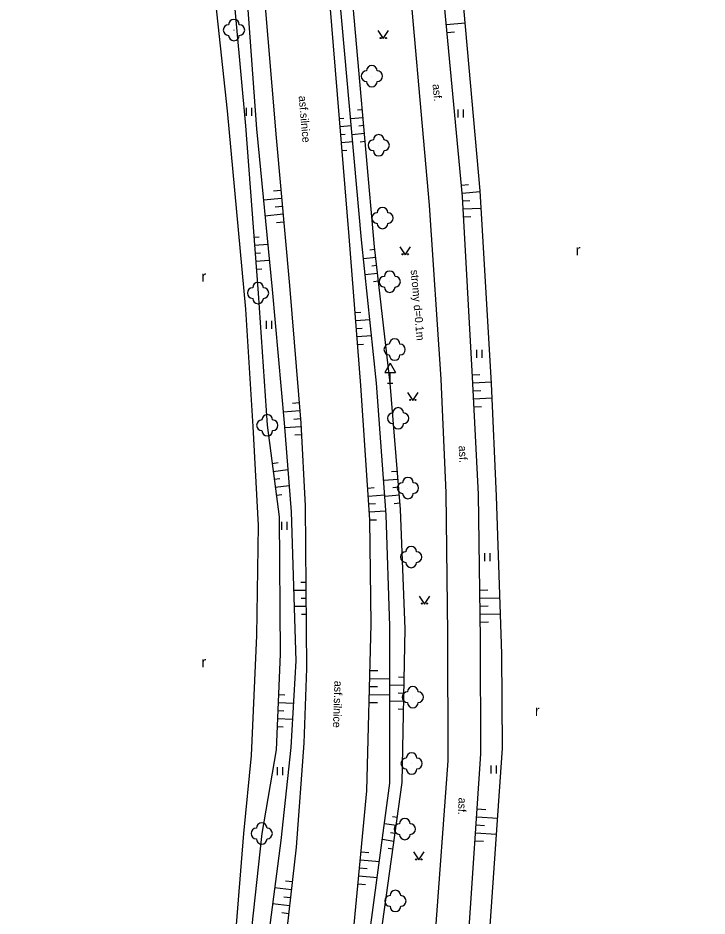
# Model space of a CAD drawing. Extents: x -545714 to -535419, y -1201788 to -1194297.
# Drawn here: x -543649.7 to -543585.1, y -1196035 to -1195950.8 of the extents above; entities that cross this region are included whole.
import ezdxf

# ---------------------------------------------------------------- set-up
doc = ezdxf.new("R2010")
doc.units = 0
for name, color, linetype in [('Vrstva 10', 7, 'Continuous'), ('Vrstva 11', 7, 'Continuous'), ('Vrstva 12', 7, 'Continuous'), ('Vrstva 13', 7, 'Continuous'), ('Vrstva 15', 7, 'Continuous'), ('Vrstva 3', 7, 'Continuous')]:
    doc.layers.add(name, color=color, linetype=linetype)

msp = doc.modelspace()

# ---------------------------------------------------------------- linework, layer by layer
at = {"layer": 'Vrstva 10'}
for p, q in [((-543614.79, -1195983.134), (-543615.29, -1195984)), ((-543614.79, -1195983.134), (-543614.29, -1195984)), ((-543615.29, -1195984), (-543614.29, -1195984)), ((-543614.79, -1195985), (-543614.79, -1195984)), ((-543615.04, -1195985), (-543614.54, -1195985))]:
    msp.add_line(p, q, dxfattribs=at)
at = {"layer": 'Vrstva 11'}
for points in [[(-543607.43, -1196037.02), (-543606.28, -1196019.77), (-543606.3, -1196009), (-543606.5, -1195995.43), (-543607.06, -1195984.44), (-543608.01, -1195967.52), (-543610.49, -1195940.94), (-543612.66, -1195916.66), (-543613.72, -1195904.08), (-543614, -1195894.09), (-543612.96, -1195887.23), (-543612.45, -1195879.29), (-543612.44, -1195876.36), (-543611.47, -1195876.49), (-543610.1, -1195878.26), (-543608.46, -1195876.99), (-543612.9, -1195869.72), (-543613.03, -1195867.25)], [(-543632.41, -1196211.07), (-543630.37, -1196193.32), (-543624.96, -1196151.17), (-543622.81, -1196132.43), (-543618.85, -1196100.43), (-543615.34, -1196072.49), (-543612.05, -1196046.99), (-543610.57, -1196036.97), (-543609.35, -1196020.42), (-543609.38, -1196008.52), (-543609.53, -1195995.3), (-543610, -1195984.65), (-543611.08, -1195968.31), (-543613.38, -1195942.54), (-543615.71, -1195916.87), (-543616.79, -1195903.73), (-543617.14, -1195895.44), (-543615.68, -1195885.08), (-543615.46, -1195880.81), (-543615.86, -1195867.87)], [(-543639.09, -1196203.64), (-543635.02, -1196171.2), (-543630.55, -1196134.22), (-543626.42, -1196101.45), (-543622.95, -1196075.4), (-543619.74, -1196048.22), (-543618.21, -1196036.42), (-543616.96, -1196023.24), (-543616.56, -1196007.59), (-543616.68, -1195997.82), (-543617.53, -1195985.22), (-543618.61, -1195971.27), (-543620.62, -1195946.9), (-543623.05, -1195920.62), (-543624.43, -1195906.58), (-543625.23, -1195895.93), (-543626.15, -1195884.51)], [(-543632.01, -1195889.02), (-543630.66, -1195904.04), (-543629.59, -1195915.71), (-543627.44, -1195938.51), (-543625.46, -1195962.01), (-543624.21, -1195975.84), (-543623.14, -1195988.77), (-543622.74, -1195996.52), (-543622.61, -1196011.77), (-543622.88, -1196018.77), (-543623.58, -1196028.52), (-543624.79, -1196039.27), (-543627.41, -1196061.04), (-543629.27, -1196076.23), (-543632.15, -1196098.41), (-543634.76, -1196118.38), (-543637.1, -1196136.86), (-543638.96, -1196152.81), (-543641.47, -1196173.25), (-543643.67, -1196191.48), (-543644.99, -1196202.76)]]:
    msp.add_lwpolyline(points, dxfattribs=at)
at = {"layer": 'Vrstva 12'}
for points in [[(-543637.35, -1195889.08), (-543636.25, -1195900.75), (-543634.27, -1195918.95), (-543632.55, -1195936.22), (-543630.06, -1195959.48), (-543628.32, -1195978.08), (-543627.64, -1195989.06), (-543627.13, -1195998.35), (-543627.3, -1196008.65), (-543627.81, -1196019.91), (-543628.52, -1196027.23), (-543629.59, -1196040.43), (-543631.56, -1196057.77), (-543633.61, -1196077.67), (-543635.95, -1196095.36), (-543638.88, -1196118.45), (-543640.59, -1196133.76), (-543643.14, -1196154.34), (-543645.07, -1196170.53), (-543648, -1196190.91), (-543649.65, -1196200.28)], [(-543620.94, -1196214.98), (-543624.31, -1196211.9), (-543626.03, -1196206.25), (-543625.47, -1196195.96), (-543620.17, -1196152.27), (-543617.52, -1196130.8), (-543613.54, -1196101.25), (-543610.23, -1196073.03), (-543606.7, -1196046.58), (-543605.55, -1196038.14), (-543604.25, -1196019.22), (-543604.31, -1196010.39), (-543604.8, -1195995.59), (-543605.27, -1195985.05), (-543606.35, -1195966.98), (-543608.76, -1195939.98), (-543609.96, -1195918.4), (-543608.87, -1195913.01), (-543606.32, -1195907.39), (-543600.46, -1195896.38), (-543598.68, -1195894.64), (-543593.62, -1195901.24), (-543585.09, -1195909.68)]]:
    msp.add_lwpolyline(points, dxfattribs=at)
for centre in [(-543629.41, -1195951.91), (-543616.49, -1195956.23), (-543615.85, -1195962.71), (-543615.5, -1195969.53), (-543614.82, -1195975.5), (-543627.16, -1195976.56), (-543614.36, -1195981.86), (-543614.03, -1195988.3), (-543626.29, -1195988.96), (-543613.11, -1195994.84), (-543612.81, -1196001.31), (-543612.65, -1196014.44), (-543612.77, -1196020.66), (-543626.81, -1196027.23), (-543613.4, -1196026.81), (-543614.29, -1196033.55)]:
    msp.add_circle(centre, 0.0005, dxfattribs=at)
for centre, start, end in [((-543629.91, -1195951.91), 89.99999, 269.99999), ((-543629.41, -1195951.41), 0, 179.99999), ((-543628.91, -1195951.91), 270, 89.99999), ((-543629.41, -1195952.41), 179.99999, 359.99999), ((-543616.99, -1195956.23), 89.99999, 269.99999), ((-543616.49, -1195955.73), 0, 179.99999), ((-543615.99, -1195956.23), 270, 89.99999), ((-543616.49, -1195956.73), 179.99999, 359.99999), ((-543616.35, -1195962.71), 89.99999, 269.99999), ((-543615.85, -1195962.21), 0, 179.99999), ((-543615.35, -1195962.71), 270, 89.99999), ((-543615.85, -1195963.21), 179.99999, 359.99999), ((-543616, -1195969.53), 89.99999, 269.99999), ((-543615.5, -1195969.03), 0, 179.99999), ((-543615, -1195969.53), 270, 89.99999), ((-543615.5, -1195970.03), 179.99999, 359.99999), ((-543615.32, -1195975.5), 89.99999, 269.99999), ((-543614.82, -1195975), 0, 179.99999), ((-543614.32, -1195975.5), 270, 89.99999), ((-543627.16, -1195976.06), 0, 179.99999), ((-543627.66, -1195976.56), 89.99999, 269.99999), ((-543626.66, -1195976.56), 270, 89.99999), ((-543614.82, -1195976), 179.99999, 359.99999), ((-543627.16, -1195977.06), 179.99999, 359.99999), ((-543614.36, -1195981.36), 0, 179.99999), ((-543614.86, -1195981.86), 89.99999, 269.99999), ((-543613.86, -1195981.86), 270, 89.99999), ((-543614.36, -1195982.36), 179.99999, 359.99999), ((-543614.03, -1195987.8), 0, 179.99999), ((-543626.79, -1195988.96), 89.99999, 269.99999), ((-543626.29, -1195988.46), 0, 179.99999), ((-543625.79, -1195988.96), 270, 89.99999), ((-543614.53, -1195988.3), 89.99999, 269.99999), ((-543613.53, -1195988.3), 270, 89.99999), ((-543614.03, -1195988.8), 179.99999, 359.99999), ((-543626.29, -1195989.46), 179.99999, 359.99999), ((-543613.61, -1195994.84), 89.99999, 269.99999), ((-543613.11, -1195994.34), 0, 179.99999), ((-543612.61, -1195994.84), 270, 89.99999), ((-543613.11, -1195995.34), 179.99999, 359.99999), ((-543612.81, -1196000.81), 0, 179.99999), ((-543613.31, -1196001.31), 89.99999, 269.99999), ((-543612.31, -1196001.31), 270, 89.99999), ((-543612.81, -1196001.81), 179.99999, 359.99999), ((-543612.65, -1196013.94), 0, 179.99999), ((-543613.15, -1196014.44), 89.99999, 269.99999), ((-543612.15, -1196014.44), 270, 89.99999), ((-543612.65, -1196014.94), 179.99999, 359.99999), ((-543612.77, -1196020.16), 0, 179.99999), ((-543613.27, -1196020.66), 89.99999, 269.99999), ((-543612.27, -1196020.66), 270, 89.99999), ((-543612.77, -1196021.16), 179.99999, 359.99999), ((-543626.81, -1196026.73), 0, 179.99999), ((-543613.9, -1196026.81), 89.99999, 269.99999), ((-543613.4, -1196026.31), 0, 179.99999), ((-543612.9, -1196026.81), 270, 89.99999), ((-543627.31, -1196027.23), 89.99999, 269.99999), ((-543626.31, -1196027.23), 270, 89.99999), ((-543613.4, -1196027.31), 179.99999, 359.99999), ((-543626.81, -1196027.73), 179.99999, 359.99999), ((-543614.79, -1196033.55), 89.99999, 269.99999), ((-543614.29, -1196033.05), 0, 179.99999), ((-543613.79, -1196033.55), 270, 89.99999), ((-543614.29, -1196034.05), 179.99999, 359.99999)]:
    msp.add_arc(centre, 0.5, start, end, dxfattribs=at)
at = {"layer": 'Vrstva 13'}
for points in [[(-543637.68, -1196204.91), (-543633.55, -1196170.77), (-543629.08, -1196133.41), (-543625.09, -1196102.26), (-543621.67, -1196075.01), (-543618.41, -1196048.88), (-543616.7, -1196036.73), (-543614.81, -1196022.52), (-543614.82, -1196007.8), (-543615.15, -1195997.35), (-543616.06, -1195985.01), (-543617.47, -1195971.56), (-543619.73, -1195946.13), (-543622.24, -1195919.83), (-543623.14, -1195907.11), (-543624.18, -1195895.5), (-543625.27, -1195884.41)], [(-543637.05, -1196204.96), (-543632.44, -1196170.19), (-543627.94, -1196133.03), (-543624.22, -1196102.84), (-543620.55, -1196074.64), (-543617.37, -1196049.43), (-543615.66, -1196036.82), (-543613.64, -1196022.43), (-543613.38, -1196008.04), (-543613.8, -1195996.84), (-543614.79, -1195985), (-543616.24, -1195972.22), (-543618.58, -1195945.75), (-543620.93, -1195921.24), (-543621.68, -1195907.9), (-543622.76, -1195895.51), (-543623.49, -1195886.82)], [(-543634.72, -1195888.98), (-543633.71, -1195902.59), (-543632.22, -1195917.58), (-543630.51, -1195936.95), (-543628.32, -1195960.9), (-543627.16, -1195976.56), (-543626.29, -1195988.96), (-543625.18, -1195997.54), (-543625.08, -1196010.41), (-543625.45, -1196019.37), (-543626.81, -1196027.23), (-543628.09, -1196039), (-543629.96, -1196058.78), (-543632.18, -1196076.05), (-543634.6, -1196096.72), (-543637.55, -1196118.36), (-543639.29, -1196135.15), (-543642.06, -1196154.03), (-543643.93, -1196171.42), (-543646.59, -1196191.4), (-543647.93, -1196200.94)], [(-543633.26, -1195889.08), (-543632.32, -1195903.25), (-543630.88, -1195916.7), (-543629.01, -1195937.51), (-543627.31, -1195961.18), (-543625.83, -1195976.22), (-543624.72, -1195988.72), (-543624.05, -1195997.08), (-543623.61, -1196011.03), (-543624.09, -1196019.16), (-543625.02, -1196027.87), (-543626.53, -1196039.42), (-543628.92, -1196059.75), (-543630.9, -1196076.27), (-543633.64, -1196097.53), (-543636.3, -1196118.46), (-543638.55, -1196135.87), (-543640.73, -1196153.47), (-543642.99, -1196172.25), (-543645.26, -1196191.46), (-543646.43, -1196201.58)], [(-543609.51, -1195951.39), (-543607.76, -1195951.23)], [(-543609.45, -1195952.14), (-543608.74, -1195952.07)], [(-543617.38, -1195959.38), (-543617.84, -1195959.42)], [(-543619.52, -1195960.2), (-543619.11, -1195960.17)], [(-543617.31, -1195960.13), (-543618.48, -1195960.23)], [(-543619.46, -1195960.95), (-543618.42, -1195960.86)], [(-543617.18, -1195961.62), (-543618.34, -1195961.73)], [(-543617.24, -1195960.87), (-543617.71, -1195960.92)], [(-543619.4, -1195961.7), (-543618.98, -1195961.66)], [(-543619.34, -1195962.44), (-543618.29, -1195962.36)], [(-543617.11, -1195962.37), (-543617.58, -1195962.41)], [(-543619.28, -1195963.19), (-543618.85, -1195963.16)], [(-543608.11, -1195966.44), (-543607.43, -1195966.38)], [(-543625.01, -1195966.94), (-543625.7, -1195967)], [(-543608.04, -1195967.19), (-543606.35, -1195967.03)], [(-543624.95, -1195967.69), (-543626.65, -1195967.84)], [(-543607.99, -1195967.93), (-543607.31, -1195967.9)], [(-543624.81, -1195969.18), (-543626.51, -1195969.34)], [(-543624.88, -1195968.44), (-543625.56, -1195968.5)], [(-543607.94, -1195968.68), (-543606.25, -1195968.59)], [(-543624.74, -1195969.93), (-543625.42, -1195969.99)], [(-543607.9, -1195969.43), (-543607.23, -1195969.39)], [(-543627.55, -1195971.33), (-543627.06, -1195971.29)], [(-543627.49, -1195972.07), (-543626.25, -1195971.98)], [(-543616.21, -1195972.48), (-543616.67, -1195972.53)], [(-543627.44, -1195972.82), (-543626.93, -1195972.79)], [(-543616.13, -1195973.23), (-543617.28, -1195973.36)], [(-543627.38, -1195973.57), (-543626.1, -1195973.48)], [(-543616.04, -1195973.97), (-543616.51, -1195974.03)], [(-543627.33, -1195974.32), (-543626.81, -1195974.28)], [(-543615.96, -1195974.72), (-543617.13, -1195974.85)], [(-543615.87, -1195975.46), (-543616.34, -1195975.52)], [(-543618.06, -1195978.4), (-543617.54, -1195978.36)], [(-543618, -1195979.14), (-543616.69, -1195979.04)], [(-543617.94, -1195979.89), (-543617.41, -1195979.85)], [(-543617.88, -1195980.64), (-543616.53, -1195980.53)], [(-543617.83, -1195981.39), (-543617.28, -1195981.34)], [(-543607.07, -1195984.23), (-543606.37, -1195984.19)], [(-543607.03, -1195984.98), (-543605.28, -1195984.89)], [(-543606.99, -1195985.73), (-543606.29, -1195985.69)], [(-543623.3, -1195986.86), (-543623.93, -1195986.92)], [(-543606.96, -1195986.48), (-543605.21, -1195986.39)], [(-543623.24, -1195987.61), (-543624.81, -1195987.74)], [(-543606.92, -1195987.22), (-543606.22, -1195987.19)], [(-543623.17, -1195988.36), (-543623.8, -1195988.41)], [(-543623.12, -1195989.11), (-543624.68, -1195989.19)], [(-543623.08, -1195989.86), (-543623.7, -1195989.89)], [(-543625.83, -1195992.53), (-543625.27, -1195992.46)], [(-543625.73, -1195993.28), (-543624.37, -1195993.1)], [(-543614.1, -1195993.28), (-543614.64, -1195993.32)], [(-543625.64, -1195994.02), (-543625.1, -1195993.95)], [(-543614.04, -1195994.03), (-543615.39, -1195994.14)], [(-543625.54, -1195994.77), (-543624.25, -1195994.6)], [(-543616.88, -1195994.84), (-543616.27, -1195994.8)], [(-543613.97, -1195994.77), (-543614.52, -1195994.82)], [(-543625.44, -1195995.51), (-543624.94, -1195995.44)], [(-543616.83, -1195995.59), (-543615.29, -1195995.48)], [(-543613.91, -1195995.52), (-543615.28, -1195995.64)], [(-543616.78, -1195996.33), (-543616.16, -1195996.29)], [(-543616.73, -1195997.08), (-543615.18, -1195996.98)], [(-543613.85, -1195996.27), (-543614.4, -1195996.32)], [(-543616.68, -1195997.83), (-543616.06, -1195997.82)], [(-543622.68, -1196003.69), (-543623.14, -1196003.69)], [(-543622.67, -1196004.44), (-543623.82, -1196004.45)], [(-543606.37, -1196004.4), (-543605.62, -1196004.39)], [(-543622.67, -1196005.19), (-543623.12, -1196005.19)], [(-543606.36, -1196005.15), (-543604.48, -1196005.12)], [(-543622.66, -1196005.94), (-543623.77, -1196005.95)], [(-543606.35, -1196005.9), (-543605.59, -1196005.89)], [(-543622.65, -1196006.69), (-543623.09, -1196006.69)], [(-543606.33, -1196006.65), (-543604.43, -1196006.62)], [(-543606.32, -1196007.4), (-543605.56, -1196007.39)], [(-543616.67, -1196011.93), (-543615.93, -1196011.95)], [(-543616.69, -1196012.68), (-543614.82, -1196012.73)], [(-543613.46, -1196012.59), (-543614, -1196012.58)], [(-543616.71, -1196013.43), (-543615.95, -1196013.45)], [(-543613.48, -1196013.34), (-543614.82, -1196013.31)], [(-543625.24, -1196014.19), (-543624.66, -1196014.21)], [(-543616.73, -1196014.18), (-543614.82, -1196014.23)], [(-543613.49, -1196014.09), (-543614.02, -1196014.08)], [(-543625.27, -1196014.94), (-543623.84, -1196015)], [(-543616.75, -1196014.93), (-543615.97, -1196014.95)], [(-543613.5, -1196014.84), (-543614.82, -1196014.81)], [(-543625.3, -1196015.69), (-543624.73, -1196015.71)], [(-543613.52, -1196015.59), (-543614.04, -1196015.58)], [(-543625.36, -1196017.19), (-543624.81, -1196017.21)], [(-543625.33, -1196016.44), (-543623.93, -1196016.5)], [(-543606.62, -1196024.91), (-543605.83, -1196024.96)], [(-543614.21, -1196026.47), (-543615.32, -1196026.32)], [(-543614.1, -1196025.73), (-543614.55, -1196025.67)], [(-543606.72, -1196026.4), (-543605.93, -1196026.46)], [(-543606.67, -1196025.66), (-543604.7, -1196025.79)], [(-543614.31, -1196027.22), (-543614.75, -1196027.15)], [(-543606.77, -1196027.15), (-543604.8, -1196027.28)], [(-543614.42, -1196027.96), (-543615.51, -1196027.8)], [(-543606.82, -1196027.9), (-543606.04, -1196027.95)], [(-543617.5, -1196028.94), (-543616.78, -1196029.01)], [(-543614.52, -1196028.7), (-543614.96, -1196028.64)], [(-543617.57, -1196029.69), (-543615.79, -1196029.86)], [(-543617.64, -1196030.44), (-543616.94, -1196030.5)], [(-543617.71, -1196031.18), (-543615.98, -1196031.35)], [(-543624.03, -1196032.5), (-543625.6, -1196032.33)], [(-543623.94, -1196031.76), (-543624.57, -1196031.69)], [(-543617.78, -1196031.93), (-543617.1, -1196031.99)], [(-543624.11, -1196033.25), (-543624.75, -1196033.18)], [(-543624.2, -1196033.99), (-543625.8, -1196033.81)], [(-543624.28, -1196034.74), (-543624.93, -1196034.67)]]:
    msp.add_lwpolyline(points, dxfattribs=at)
at = {"layer": 'Vrstva 3'}
for p, q in [((-543628.24, -1195959.935), (-543628.24, -1195959.185)), ((-543627.74, -1195959.935), (-543627.74, -1195959.185)), ((-543608.4, -1195960.095), (-543608.4, -1195959.345)), ((-543607.9, -1195960.095), (-543607.9, -1195959.345)), ((-543626.36, -1195979.905), (-543626.36, -1195979.155)), ((-543625.86, -1195979.905), (-543625.86, -1195979.155)), ((-543606.65, -1195982.635), (-543606.65, -1195981.885)), ((-543606.15, -1195982.635), (-543606.15, -1195981.885)), ((-543624.94, -1195998.765), (-543624.94, -1195998.015)), ((-543624.44, -1195998.765), (-543624.44, -1195998.015)), ((-543605.91, -1196001.695), (-543605.91, -1196000.945)), ((-543605.41, -1196001.695), (-543605.41, -1196000.945)), ((-543625.34, -1196021.765), (-543625.34, -1196021.015)), ((-543624.84, -1196021.765), (-543624.84, -1196021.015)), ((-543605.31, -1196021.595), (-543605.31, -1196020.845)), ((-543604.81, -1196021.595), (-543604.81, -1196020.845))]:
    msp.add_line(p, q, dxfattribs=at)
for points in [[(-543615.92, -1195951.96), (-543615.42, -1195952.71), (-543614.92, -1195951.96)], [(-543613.87, -1195972.23), (-543613.37, -1195972.98), (-543612.87, -1195972.23)], [(-543613.15, -1195985.88), (-543612.65, -1195986.63), (-543612.15, -1195985.88)], [(-543612.06, -1196004.97), (-543611.56, -1196005.72), (-543611.06, -1196004.97)], [(-543612.59, -1196028.95), (-543612.09, -1196029.7), (-543611.59, -1196028.95)]]:
    msp.add_lwpolyline(points, dxfattribs=at)
for centre in [(-543615.67, -1195952.66), (-543615.17, -1195952.66), (-543613.62, -1195972.93), (-543613.12, -1195972.93), (-543612.9, -1195986.58), (-543612.4, -1195986.58), (-543611.81, -1196005.67), (-543611.31, -1196005.67), (-543612.34, -1196029.65), (-543611.84, -1196029.65)]:
    msp.add_circle(centre, 0.05, dxfattribs=at)

# ---------------------------------------------------------------- texts
at = {"layer": 'Vrstva 12'}
msp.add_text('stromy d=0.1m', height=0.75, rotation=274.91088, dxfattribs=at).set_placement((-543612.86, -1195974.41))
at = {"layer": 'Vrstva 15'}
for s, rotation, p in [('asf.', 275.10018, (-543610.81, -1195957)), ('asf.silnice', 274.81611, (-543623.35, -1195958.1)), ('asf.', 272.52692, (-543608.36, -1195990.88)), ('asf.silnice', 268.00926, (-543619.99, -1196012.9)), ('asf.', 267.54218, (-543608.36, -1196023.85))]:
    msp.add_text(s, height=0.75, rotation=rotation, dxfattribs=at).set_placement(p)
at = {"layer": 'Vrstva 3'}
for p in [(-543597.398, -1195973.032), (-543632.468, -1195975.502), (-543632.468, -1196011.652), (-543601.218, -1196016.212)]:
    msp.add_text('r', height=1, dxfattribs=at).set_placement(p)

doc.saveas('drawing.dxf')
